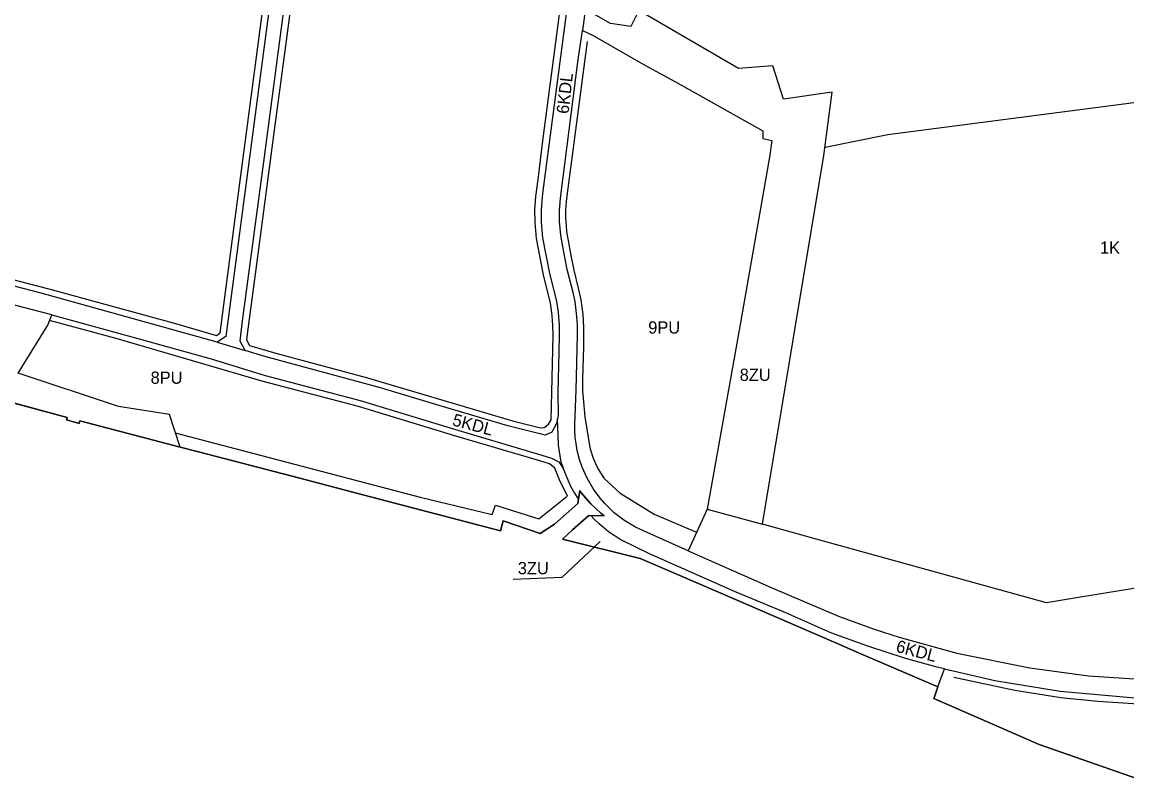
# Model space of a CAD drawing. Extents: x 7428203 to 7432868, y 5542672 to 5545406.
# Drawn here: x 7428940 to 7429842, y 5543796 to 5544419 of the extents above; entities that cross this region are included whole.
import ezdxf

# ---------------------------------------------------------------- set-up
doc = ezdxf.new("R2010")
doc.units = 0
for name, color, linetype in [('__LEGENDA_RAMKA_LOGO_PODZIAŁKA', 7, 'Continuous'), ('_GRANICA_MIASTA', 7, 'Continuous'), ('granicaBulwary', 7, 'Continuous'), ('MPZP_uchwalone_nieobowiazujace jeszcze_SZRAF', 7, 'Continuous')]:
    doc.layers.add(name, color=color, linetype=linetype)

msp = doc.modelspace()

# ---------------------------------------------------------------- linework, layer by layer
at = {"layer": '__LEGENDA_RAMKA_LOGO_PODZIAŁKA'}
msp.add_lwpolyline([(7428860.8, 5544127.52), (7428976.57, 5544096.41), (7428976.04, 5544094.28), (7428986.46, 5544091.47), (7428986.99, 5544093.6), (7429068.86, 5544072.19), (7429083.71, 5544068.31), (7429166.46, 5544046.67), (7429219.11, 5544032.89), (7429330.2, 5544003.84), (7429332.52, 5544011.99), (7429362.52, 5544001.5), (7429374.21, 5544009.14), (7429393.34, 5544026.23), (7429395, 5544036.69), (7429396.19, 5544034.81), (7429403.87, 5544025.95), (7429412.05, 5544018.34), (7429414.91, 5544016.13), (7429402.37, 5544016.42), (7429389.04, 5544004.48), (7429380.81, 5543997.1), (7429444.36, 5543981.21), (7429474.6, 5543968.15), (7429521.96, 5543947.71), (7429604.6, 5543912.04), (7429622.53, 5543904.3), (7429670.15, 5543883.75), (7429687.25, 5543876.37), (7429684.97, 5543869.82), (7429684, 5543866.99), (7429769.93, 5543829.29), (7429864.43, 5543796.42)], dxfattribs=at)
at = {"layer": '_GRANICA_MIASTA'}
for p, q in [((7429099.14, 5544157.86), (7429121.95, 5544150.94)), ((7428976.57, 5544096.41), (7428860.8, 5544127.52)), ((7428976.04, 5544094.28), (7428976.57, 5544096.41)), ((7428986.46, 5544091.47), (7428976.04, 5544094.28)), ((7428986.99, 5544093.6), (7428986.46, 5544091.47)), ((7429068.86, 5544072.19), (7428986.99, 5544093.6)), ((7429083.71, 5544068.31), (7429068.86, 5544072.19)), ((7429166.46, 5544046.67), (7429083.71, 5544068.31)), ((7429219.11, 5544032.89), (7429166.46, 5544046.67)), ((7429330.2, 5544003.84), (7429219.11, 5544032.89)), ((7429395, 5544036.69), (7429393.34, 5544026.23)), ((7429396.19, 5544034.81), (7429395, 5544036.69)), ((7429403.87, 5544025.95), (7429396.19, 5544034.81)), ((7429393.34, 5544026.23), (7429374.21, 5544009.14)), ((7429412.05, 5544018.34), (7429403.87, 5544025.95)), ((7429332.52, 5544011.99), (7429330.2, 5544003.84)), ((7429362.52, 5544001.5), (7429332.52, 5544011.99)), ((7429389.04, 5544004.48), (7429402.37, 5544016.42)), ((7429402.37, 5544016.42), (7429414.91, 5544016.13)), ((7429414.91, 5544016.13), (7429412.05, 5544018.34)), ((7429374.21, 5544009.14), (7429362.52, 5544001.5)), ((7429380.81, 5543997.1), (7429389.04, 5544004.48)), ((7429444.36, 5543981.21), (7429380.81, 5543997.1)), ((7429474.6, 5543968.15), (7429444.36, 5543981.21)), ((7429521.96, 5543947.71), (7429474.6, 5543968.15)), ((7429604.6, 5543912.04), (7429521.96, 5543947.71)), ((7429622.53, 5543904.3), (7429604.6, 5543912.04)), ((7429670.15, 5543883.75), (7429622.53, 5543904.3)), ((7429687.25, 5543876.37), (7429670.15, 5543883.75)), ((7429684.97, 5543869.82), (7429687.25, 5543876.37)), ((7429684, 5543866.99), (7429684.97, 5543869.82)), ((7429769.93, 5543829.29), (7429684, 5543866.99)), ((7429864.43, 5543796.42), (7429769.93, 5543829.29))]:
    msp.add_line(p, q, dxfattribs=at)
for points in [[(7429198.67, 5544727.47), (7429176.49, 5544739.59), (7429181.27, 5544730.14), (7429139.09, 5544411.72), (7429106.05, 5544162.35), (7429099.14, 5544157.86), (7428955.29, 5544197.85), (7428805.14, 5544236.81), (7428800.36, 5544244.12), (7428835.48, 5544505.35), (7428871.87, 5544782.58), (7428886.98, 5544894.27), (7428893.15, 5544897.22), (7428979.15, 5544848.51), (7428994.76, 5544839.83), (7428990.64, 5544827.77), (7428982.93, 5544761.65), (7428979.22, 5544729.83), (7429033.78, 5544721.61), (7429045.31, 5544798.17), (7429047.66, 5544810.44), (7429085.54, 5544789.39), (7429155.84, 5544750.87), (7429176.49, 5544739.59)], [(7428964.08, 5544180.06), (7429037.36, 5544159.85), (7429094.05, 5544144.08), (7429138.08, 5544130.52), (7429215.73, 5544110.08), (7429295.33, 5544085.88), (7429354, 5544068.58), (7429364.09, 5544065.6), (7429371.99, 5544063.24), (7429378.01, 5544060.16), (7429381.22, 5544055.34), (7429381.99, 5544053.37), (7429381.64, 5544054.57), (7429379.86, 5544059.92), (7429377.73, 5544073.72), (7429377.26, 5544081.59), (7429376.71, 5544095.24), (7429375.93, 5544091.53), (7429372.24, 5544084.33), (7429366.79, 5544081.9), (7429336.24, 5544089.46), (7429281.08, 5544105.73), (7429232.22, 5544120.6), (7429137.95, 5544146.09), (7429121.95, 5544150.94), (7429117.72, 5544158.72), (7429119.57, 5544172.92), (7429137.15, 5544304.86), (7429192.3, 5544724.11)], [(7429389.85, 5544471.47), (7429364.8, 5544281.38), (7429364.17, 5544276.36), (7429363.43, 5544265.84), (7429363.45, 5544255.69), (7429364.63, 5544242.97), (7429370.15, 5544213.76), (7429375.88, 5544191.22), (7429377.31, 5544181.97), (7429378.07, 5544171.5), (7429378.15, 5544163.57), (7429377.9, 5544149.97), (7429377.05, 5544117.07), (7429377.29, 5544097.94), (7429376.71, 5544095.24)], [(7429399.4, 5544428.49), (7429397.26, 5544412.31), (7429406.02, 5544407.99), (7429447.97, 5544383.8), (7429473.2, 5544370.15), (7429544.5, 5544330.23), (7429544.47, 5544323.93), (7429551.8, 5544322.49), (7429549.72, 5544308.79), (7429525.07, 5544167.56), (7429498.93, 5544021.41), (7429543.98, 5544009.32), (7429594.13, 5544310.09), (7429600.95, 5544361.82), (7429561.15, 5544356.18), (7429552.57, 5544383.46), (7429524.5, 5544381.03), (7429443.24, 5544428.41), (7429436.74, 5544415.56), (7429420.03, 5544417.78), (7429406.07, 5544425.77)], [(7429498.93, 5544021.41), (7429483.45, 5543987.53), (7429450.08, 5544002.33), (7429440.43, 5544006.83), (7429430.98, 5544012.53), (7429423.1, 5544018.6), (7429415.44, 5544025.99), (7429411.66, 5544030.34), (7429406.17, 5544037.82), (7429401.02, 5544046.66), (7429396.97, 5544055.78), (7429394.86, 5544061.96), (7429392.96, 5544069.31), (7429391.91, 5544075.12), (7429391.32, 5544079.85), (7429390.94, 5544085.76), (7429390.91, 5544090.5), (7429392.09, 5544118.74), (7429393.15, 5544163.51), (7429393.06, 5544172.05), (7429392.42, 5544181.2), (7429391.14, 5544190.91), (7429389.68, 5544198.36), (7429384.8, 5544217.01), (7429380.98, 5544237.19), (7429379.5, 5544245.06), (7429378.45, 5544256.39), (7429378.43, 5544265.32), (7429379.14, 5544275.25), (7429393.58, 5544388.64), (7429397.26, 5544412.31)], [(7429068.86, 5544072.19), (7429060.22, 5544098.67), (7429018.58, 5544105.27), (7428936.65, 5544132.38), (7428960.84, 5544171.8), (7428964.08, 5544180.06), (7428802.22, 5544221.94), (7428661.3, 5544258.99)], [(7429381.99, 5544053.37), (7429384.4, 5544047.27), (7429387.4, 5544040.36), (7429390.58, 5544034.5), (7429393.83, 5544029.35)], [(7429686.91, 5543876.52), (7429687.33, 5543876.59), (7429692.68, 5543891.06), (7429685.7, 5543892.8), (7429660.05, 5543899.99), (7429630.15, 5543909.54), (7429599.89, 5543920.53), (7429563.13, 5543936.87), (7429521.33, 5543954.32), (7429452, 5543985.07), (7429428.41, 5543996.37), (7429418.44, 5544003.09), (7429410.74, 5544009.52), (7429406.52, 5544013.6), (7429403.94, 5544016.38)], [(7429959.79, 5543974.93), (7429805.3, 5543949.82), (7429775.88, 5543945.04), (7429585.97, 5543997.5), (7429543.98, 5544009.32)], [(7429483.45, 5543987.53), (7429551.2, 5543957.47), (7429606.21, 5543934.17), (7429635.3, 5543923.63), (7429655.65, 5543917), (7429702.65, 5543903.98), (7429762.19, 5543891.88), (7429810.29, 5543885.43), (7429897.37, 5543879.68)], [(7429692.68, 5543891.06), (7429733.68, 5543881.76), (7429787.12, 5543873.02), (7429851.1, 5543867.29), (7429960.09, 5543860.73), (7429984.9, 5543859.31), (7430010.49, 5543857.85), (7430047.45, 5543855.75), (7430162.05, 5543849.26), (7430213.06, 5543846.63), (7430226.75, 5543846.71), (7430245.5, 5543848.19), (7430288.91, 5543854.44), (7430330.3, 5543860.39), (7430346.69, 5543847.34), (7430344.79, 5543892.69)]]:
    msp.add_lwpolyline(points, dxfattribs=at)
at = {"layer": 'granicaBulwary'}
msp.add_lwpolyline([(7429340.5, 5543964.36), (7429380.55, 5543965.98), (7429411.59, 5543995.04)], dxfattribs=at)
at = {"layer": 'MPZP_uchwalone_nieobowiazujace jeszcze_SZRAF'}
for p, q in [((7429646.41, 5544327.23), (7429885.23, 5544358.31)), ((7429595.21, 5544316.97), (7429646.41, 5544327.23))]:
    msp.add_line(p, q, dxfattribs=at)
msp.add_lwpolyline([(7428892.96, 5544891.59), (7428891.57, 5544890.93), (7428873.42, 5544756.02), (7428838.05, 5544486.51), (7428824.47, 5544383), (7428809.45, 5544270.11), (7428805.6, 5544245.24), (7428808.27, 5544241.17), (7428960.48, 5544201.62), (7429063.14, 5544173.58), (7429098.37, 5544163.32), (7429101.4, 5544165.29), (7429115.21, 5544269.13), (7429156.74, 5544584.47), (7429176.11, 5544729.27), (7429172.73, 5544735.95), (7429073.35, 5544790.45), (7428930.42, 5544870.37)], close=True, dxfattribs=at)
for points in [[(7429168.34, 5544502.96), (7429155.31, 5544403.82), (7429150.66, 5544369.28), (7429145.62, 5544330.94), (7429132.18, 5544229.57), (7429123.49, 5544164.28), (7429122.89, 5544159.69), (7429125.37, 5544155.13), (7429147.04, 5544148.85), (7429221.64, 5544128.64), (7429322.76, 5544098.64), (7429340.1, 5544093.62), (7429360.86, 5544088.3), (7429363.27, 5544087.93), (7429365.85, 5544088.17), (7429366.46, 5544088.37), (7429369.41, 5544090.85), (7429371.73, 5544094.28), (7429372.05, 5544117.11), (7429373.15, 5544163.59), (7429373.07, 5544171.31), (7429372.48, 5544179.62), (7429371.09, 5544189.69), (7429365.26, 5544212.68), (7429359.67, 5544242.27), (7429358.45, 5544255.45), (7429358.43, 5544266.01), (7429359.18, 5544276.71), (7429360.89, 5544290.44), (7429364.86, 5544322.25), (7429402.06, 5544605.4)], [(7429400.91, 5544403.19), (7429386.79, 5544295.83), (7429383.99, 5544272.97), (7429383.45, 5544265.36), (7429383.44, 5544259.2), (7429383.78, 5544253.07), (7429384.26, 5544247.81), (7429385.12, 5544242.24), (7429387.68, 5544228.66), (7429390.09, 5544216.48), (7429393.79, 5544201.97), (7429395.97, 5544192.35), (7429397.49, 5544180.5), (7429398.08, 5544169.66), (7429397.98, 5544154.03), (7429397.33, 5544127.64), (7429397.08, 5544117.76), (7429397.65, 5544112.16), (7429399.23, 5544096.94), (7429402.97, 5544073.48), (7429403.4, 5544070.83), (7429405.87, 5544063.23), (7429407.69, 5544058.67), (7429409.61, 5544054.72), (7429414.66, 5544046.86), (7429427.93, 5544034.62), (7429455.8, 5544017.45), (7429490.35, 5544002.62)], [(7429384.93, 5544032.13), (7429378.37, 5544045.55), (7429374.6, 5544054.83), (7429370.29, 5544058.53), (7429362.37, 5544060.9), (7429293.91, 5544081.08), (7429214.36, 5544105.27), (7429136.7, 5544125.71), (7429016.65, 5544160.8), (7428962.24, 5544175.37)], [(7429064.63, 5544083.66), (7429264.77, 5544031.29), (7429323.55, 5544017.01), (7429326.07, 5544024.84), (7429361.69, 5544013.62), (7429384.81, 5544032.03)], [(7430352.56, 5543805.37), (7430345.56, 5543820.39), (7430342.81, 5543831.42), (7430341.79, 5543844.85), (7430328.95, 5543855.08), (7430246.14, 5543843.23), (7430226.91, 5543841.71), (7430212.94, 5543841.63), (7430161.78, 5543844.27), (7430047.23, 5543850.54), (7429850.78, 5543862.3), (7429817.78, 5543864.62), (7429787.47, 5543867.62), (7429750.04, 5543873.61), (7429700.15, 5543884.05)]]:
    msp.add_lwpolyline(points, dxfattribs=at)

# ---------------------------------------------------------------- texts
at = {"layer": 'granicaBulwary'}
for s, rotation, p in [('6KDL', 83.64468, (7429385.8, 5544343.75)), ('5KDL', 345.09526, (7429290.32, 5544090)), ('6KDL', 345.09526, (7429652.37, 5543905.23))]:
    msp.add_text(s, height=10, rotation=rotation, dxfattribs=at).set_placement(p)
for s, p in [('1K', (7429819.52, 5544229.98)), ('9PU', (7429450.85, 5544164.8)), ('8PU', (7429044.71, 5544123.83)), ('8ZU', (7429525.5, 5544126.16)), ('3ZU', (7429344.41, 5543968.36))]:
    msp.add_text(s, height=10, dxfattribs=at).set_placement(p)

doc.saveas('drawing.dxf')
